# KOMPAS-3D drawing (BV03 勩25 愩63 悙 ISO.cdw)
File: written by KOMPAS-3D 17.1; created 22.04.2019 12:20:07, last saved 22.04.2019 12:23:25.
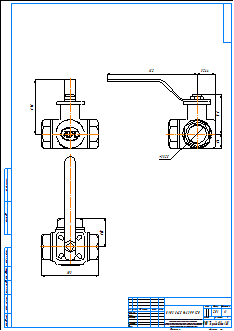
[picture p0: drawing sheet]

Sheet 1: A2, portrait

Title block, sheet 1: name: BV03 Ду25 Ру63 РР ISO; material: Внимание! Данный продукт является объектом авторского права ООО «Торговый Дом АДЛ». / Запрещается изменение, копирование, распространение / (в том числе путем копирования на другие сайты и ресурсы в Интернете) / или любое иное использование информации и объектов без предварительного / согласия правообладателя (ООО «Торговый Дом АДЛ»).; mass: 2,01; sheets: 1; organisation: ООО "Торговый дом АДЛ"; sheet format: A2

Views: Спереди 1, Проекционный вид 2, Проекционный вид 3
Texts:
  user
Dimensions and other numbers on the sheet: 97,5; 103; 51,5; 70,5; 26; 162; 32,44; 33,25; 1:1; 1; 2,01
